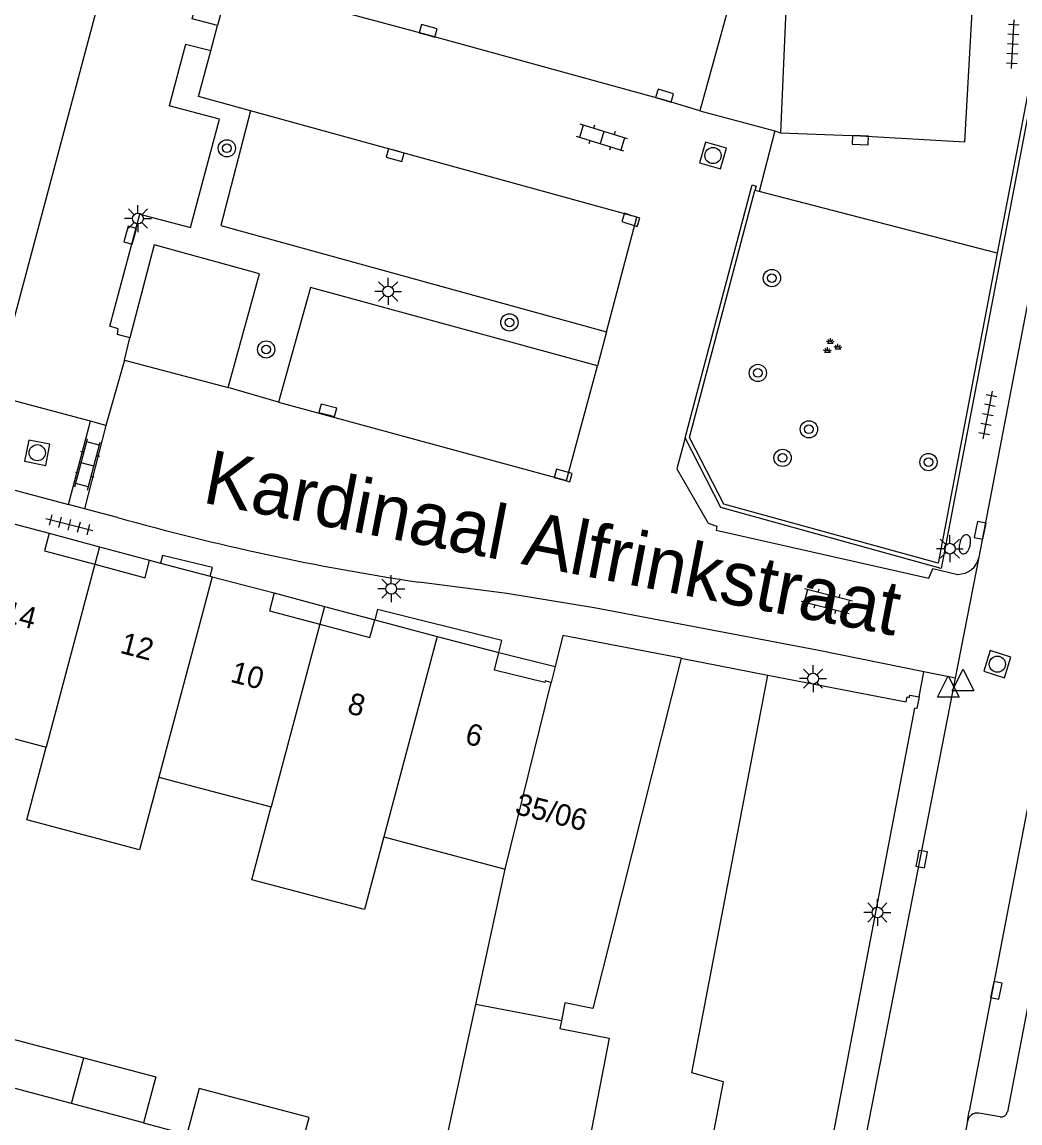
# Model space of a CAD drawing. Extents: x 132998 to 136004, y 396998 to 398512.
# Drawn here: x 133628.5 to 133674.7, y 397657 to 397708.1 of the extents above; entities that cross this region are included whole.
import ezdxf

# ---------------------------------------------------------------- set-up
doc = ezdxf.new("R2010")
doc.units = 0
for name, color, linetype in [('gg-afsc-erfafscheiding', 7, 'Continuous'), ('gg-afsc-hekwerk', 7, 'Continuous'), ('gg-afsc-muur', 7, 'Continuous'), ('gg-anno-huisnummerreeks BGT', 7, 'Continuous'), ('gg-anno-openbare ruimte label', 7, 'Continuous'), ('gg-bbg-gedigitaliseerde bebouwing', 7, 'Continuous'), ('gg-bbg-gedigitaliseerde bijgebouw', 7, 'Continuous'), ('gg-bbg-hoofdgebouw', 7, 'Continuous'), ('gg-bbg-luifel en loopbrug', 7, 'Continuous'), ('gg-bbg-onder overbouw', 7, 'Continuous'), ('gg-bbg-pand overbouw', 7, 'Continuous'), ('gg-bbg-pandafbakening', 7, 'Continuous'), ('gg-bbg-tussenscheiding', 7, 'Continuous'), ('gg-bbg-tussenscheiding niveau 01', 7, 'Continuous'), ('gg-knt-verharding', 7, 'Continuous'), ('gg-knt-verharding nz', 7, 'Continuous'), ('gt-grn-weggrens', 7, 'Continuous'), ('gt-symb-boom', 7, 'Continuous'), ('gt-symb-brandkraan', 7, 'Continuous'), ('gt-symb-groenvak', 7, 'Continuous'), ('gt-symb-klinker verharding', 7, 'Continuous'), ('gt-symb-kolk', 7, 'Continuous'), ('gt-symb-lichtmast', 7, 'Continuous'), ('gt-symb-rioolschacht', 7, 'Continuous'), ('gt-symb-tegel verharding', 7, 'Continuous'), ('gt-symb-waterafsluiter', 7, 'Continuous')]:
    doc.layers.add(name, color=color, linetype=linetype)

# ---------------------------------------------------------------- blocks, each defined once
blk = doc.blocks.new('gt0-TEG1')
at = {"layer": 'gt-symb-tegel verharding'}
for p, q in [((-1.125, 0), (1.125, 0)), ((-0.9, -0.25), (-0.9, 0.25)), ((-0.45, -0.25), (-0.45, 0.25)), ((0, -0.25), (0, 0.25)), ((0.45, -0.25), (0.45, 0.25)), ((0.9, -0.25), (0.9, 0.25))]:
    blk.add_line(p, q, dxfattribs=at)
blk = doc.blocks.new('gt0-KL1')
at = {"layer": 'gt-symb-klinker verharding'}
for p, q in [((-1.15, 0.3), (1.15, 0.3)), ((-1, -0.3), (-1, 0.3)), ((-0.5, 0.3), (-0.5, 0.45)), ((0, -0.3), (0, 0.3)), ((0.5, 0.3), (0.5, 0.45)), ((1, -0.3), (1, 0.3)), ((-1.15, -0.3), (1.15, -0.3)), ((-0.5, -0.45), (-0.5, -0.3)), ((0.5, -0.45), (0.5, -0.3))]:
    blk.add_line(p, q, dxfattribs=at)
blk = doc.blocks.new('gt0-RS')
at = {"layer": 'gt-symb-rioolschacht'}
blk.add_lwpolyline([(-0.5, -0.5), (0.5, -0.5), (0.5, 0.5), (-0.5, 0.5)], close=True, dxfattribs=at)
blk.add_circle((0, 0), 0.375, dxfattribs=at)
blk = doc.blocks.new('gt0-KOLK')
at = {"layer": 'gt-symb-kolk'}
blk.add_lwpolyline([(0, 0), (0.375, 0), (0.375, 0.4), (-0.375, 0.4), (-0.375, 0), (0, 0)], dxfattribs=at)
blk = doc.blocks.new('gt0-BOOM')
at = {"layer": 'gt-symb-boom'}
for radius in [0.4, 0.2]:
    blk.add_circle((0, 0), radius, dxfattribs=at)
blk = doc.blocks.new('gt0-GRVAK')
at = {"layer": 'gt-symb-groenvak'}
for p, q in [((-0.11, 0.189), (-0.228, 0.24)), ((-0.182, 0.153), (0.088, 0.153)), ((-0.091, 0.211), (-0.156, 0.322)), ((-0.047, 0.214), (-0.047, 0.393)), ((-0.004, 0.211), (0.061, 0.322)), ((0.015, 0.189), (0.133, 0.24)), ((0.262, -0.052), (0.197, 0.059)), ((0.305, -0.049), (0.305, 0.13)), ((0.349, -0.052), (0.414, 0.059)), ((-0.245, -0.228), (-0.363, -0.177)), ((-0.318, -0.264), (-0.047, -0.264)), ((-0.226, -0.206), (-0.291, -0.095)), ((-0.183, -0.203), (-0.183, -0.024)), ((-0.139, -0.206), (-0.074, -0.095)), ((-0.12, -0.228), (-0.002, -0.177)), ((0.243, -0.074), (0.125, -0.023)), ((0.17, -0.11), (0.441, -0.11)), ((0.368, -0.074), (0.486, -0.023))]:
    blk.add_line(p, q, dxfattribs=at)
blk = doc.blocks.new('gt0-LMAST')
at = {"layer": 'gt-symb-lichtmast'}
for p, q in [((-0.005, 0.246), (-0.005, 0.621)), ((-0.182, 0.173), (-0.447, 0.438)), ((0.172, 0.173), (0.437, 0.438)), ((-0.255, -0.004), (-0.63, -0.004)), ((-0.182, -0.181), (-0.447, -0.446)), ((-0.005, -0.254), (-0.005, -0.629)), ((0.437, -0.446), (0.172, -0.181)), ((0.245, -0.004), (0.62, -0.004))]:
    blk.add_line(p, q, dxfattribs=at)
blk.add_circle((-0.005, -0.004), 0.25, dxfattribs=at)
blk = doc.blocks.new('gt0-BR')
at = {"layer": 'gt-symb-brandkraan'}
for centre, radius, start, end in [((-0.244, 0), 0.206, 107.5669, 252.4331), ((0.599, -2.664), 3, 106.892, 107.5669), ((0, -0.691), 0.938, 73.108, 106.892), ((-0.599, -2.664), 3, 72.4331, 73.108), ((0.244, 0), 0.206, 287.567, 72.4331), ((0.599, 2.664), 3, 252.4331, 253.108), ((0, 0.691), 0.938, 253.108, 286.8921), ((-0.599, 2.664), 3, 286.8921, 287.567)]:
    blk.add_arc(centre, radius, start, end, dxfattribs=at)
blk = doc.blocks.new('gt0-WAFSL')
at = {"layer": 'gt-symb-waterafsluiter'}
for p, q in [((-0.5, -0.333), (0, 0.667)), ((0, 0.667), (0.5, -0.333)), ((0.5, -0.333), (-0.5, -0.333))]:
    blk.add_line(p, q, dxfattribs=at)

msp = doc.modelspace()

# ---------------------------------------------------------------- linework, layer by layer
at = {"layer": 'gg-afsc-erfafscheiding'}
msp.add_line((133634.128, 397657.05), (133636.141, 397656.512), dxfattribs=at)
at = {"layer": 'gg-afsc-hekwerk'}
for p, q in [((133662.654, 397700.205), (133662.457, 397700.256)), ((133673.683, 397697.355), (133662.654, 397700.205))]:
    msp.add_line(p, q, dxfattribs=at)
at = {"layer": 'gg-afsc-muur'}
for p, q in [((133679.404, 397727.312), (133673.683, 397697.355)), ((133676.965, 397713.527), (133671.086, 397682.743)), ((133673.683, 397697.355), (133670.938, 397682.981)), ((133659.037, 397678.583), (133660.057, 397678.39))]:
    msp.add_line(p, q, dxfattribs=at)
for points in [[(133659.219, 397688.791), (133662.326, 397700.513), (133662.512, 397700.463), (133662.457, 397700.256)], [(133670.938, 397682.981), (133661.009, 397685.72), (133659.423, 397688.81), (133662.457, 397700.256)], [(133671.086, 397682.743), (133660.878, 397685.559), (133659.219, 397688.791)]]:
    msp.add_lwpolyline(points, dxfattribs=at)
at = {"layer": 'gg-bbg-gedigitaliseerde bebouwing'}
for p, q in [((133624.407, 397675.848), (133629.617, 397674.462)), ((133634.845, 397673.073), (133640.045, 397671.69)), ((133645.263, 397670.304), (133650.88, 397668.811)), ((133649.52, 397662.541), (133650.88, 397668.811))]:
    msp.add_line(p, q, dxfattribs=at)
for points in [[(133659.037, 397678.583), (133654.946, 397662.357), (133653.65, 397662.606), (133653.491, 397661.781)], [(133655.15, 397628.455), (133660.998, 397658.956), (133659.526, 397659.368), (133663.055, 397677.79)], [(133634.845, 397673.073), (133633.949, 397669.702), (133628.721, 397671.092), (133629.617, 397674.462)], [(133645.263, 397670.304), (133644.366, 397666.933), (133639.149, 397668.32), (133640.045, 397671.69)], [(133642.472, 397631.33), (133646.222, 397647.335), (133649.52, 397662.541)], [(133653.491, 397661.781), (133653.421, 397661.418), (133655.7, 397660.98), (133654.378, 397654.106)]]:
    msp.add_lwpolyline(points, dxfattribs=at)
at = {"layer": 'gg-bbg-gedigitaliseerde bijgebouw'}
for p, q in [((133628.036, 397660.944), (133631.361, 397660.063)), ((133630.793, 397657.941), (133627.475, 397658.827)), ((133634.128, 397657.05), (133630.793, 397657.941))]:
    msp.add_line(p, q, dxfattribs=at)
msp.add_lwpolyline([(133631.361, 397660.063), (133634.7, 397659.178), (133634.128, 397657.05)], dxfattribs=at)
at = {"layer": 'gg-bbg-hoofdgebouw'}
for p, q in [((133626.878, 397685.133), (133629.757, 397684.374)), ((133634.412, 397683.12), (133634.921, 397682.987)), ((133634.921, 397682.987), (133637.214, 397682.385)), ((133637.214, 397682.385), (133637.315, 397682.359)), ((133637.315, 397682.359), (133640.181, 397681.608)), ((133644.839, 397680.355), (133644.844, 397680.354)), ((133644.844, 397680.354), (133647.734, 397679.596)), ((133647.734, 397679.596), (133650.594, 397678.846))]:
    msp.add_line(p, q, dxfattribs=at)
for points in [[(133627.399, 397692.591), (133627.663, 397692.521), (133635.288, 397721.118)], [(133659.037, 397678.583), (133653.55, 397679.638), (133653.195, 397678.201)], [(133663.055, 397677.79), (133669.459, 397676.564), (133669.503, 397676.79), (133669.611, 397676.769), (133669.632, 397676.877), (133670.064, 397676.793)], [(133670.064, 397676.793), (133669.959, 397676.253), (133669.851, 397676.274), (133660.537, 397627.523)]]:
    msp.add_lwpolyline(points, dxfattribs=at)
at = {"layer": 'gg-bbg-luifel en loopbrug'}
msp.add_lwpolyline([(133641.405, 397655.8), (133641.8, 397657.296), (133636.704, 397658.647), (133636.141, 397656.512)], dxfattribs=at)
at = {"layer": 'gg-bbg-onder overbouw'}
for points in [[(133629.757, 397684.374), (133629.538, 397683.56), (133631.87, 397682.933)], [(133631.87, 397682.933), (133634.199, 397682.307), (133634.412, 397683.12)], [(133640.181, 397681.608), (133639.963, 397680.779), (133642.298, 397680.161)], [(133642.298, 397680.161), (133644.614, 397679.547), (133644.839, 397680.355)], [(133653.013, 397677.464), (133652.741, 397677.531), (133652.722, 397677.453), (133650.392, 397678.031), (133650.594, 397678.846)]]:
    msp.add_lwpolyline(points, dxfattribs=at)
at = {"layer": 'gg-bbg-pand overbouw'}
for p, q in [((133629.757, 397684.374), (133632.086, 397683.746)), ((133632.086, 397683.746), (133634.412, 397683.12)), ((133640.181, 397681.608), (133642.516, 397680.98)), ((133642.516, 397680.98), (133644.839, 397680.355)), ((133650.594, 397678.846), (133653.195, 397678.201))]:
    msp.add_line(p, q, dxfattribs=at)
at = {"layer": 'gg-bbg-pandafbakening'}
msp.add_line((133653.195, 397678.201), (133653.013, 397677.464), dxfattribs=at)
at = {"layer": 'gg-bbg-tussenscheiding'}
for p, q in [((133631.87, 397682.933), (133629.617, 397674.462)), ((133637.315, 397682.359), (133634.845, 397673.073)), ((133642.298, 397680.161), (133640.045, 397671.69)), ((133647.734, 397679.596), (133645.263, 397670.304)), ((133650.88, 397668.811), (133653.013, 397677.464)), ((133653.491, 397661.781), (133649.52, 397662.541)), ((133630.793, 397657.941), (133631.361, 397660.063))]:
    msp.add_line(p, q, dxfattribs=at)
at = {"layer": 'gg-bbg-tussenscheiding niveau 01'}
for p, q in [((133632.086, 397683.746), (133631.87, 397682.933)), ((133642.516, 397680.98), (133642.298, 397680.161))]:
    msp.add_line(p, q, dxfattribs=at)
at = {"layer": 'gg-knt-verharding'}
for p, q in [((133638.105, 397709.933), (133637.553, 397707.902)), ((133659.907, 397703.94), (133663.386, 397703.015)), ((133663.386, 397703.015), (133662.654, 397700.205)), ((133663.386, 397703.015), (133663.645, 397702.933)), ((133573.036, 397701.017), (133630.659, 397685.707)), ((133672.84, 397683.259), (133675.574, 397697.514)), ((133655.572, 397693.705), (133655.168, 397692.133)), ((133633.251, 397692.388), (133633.496, 397693.43)), ((133633.251, 397692.388), (133632.391, 397689.373)), ((133640.391, 397690.454), (133638.053, 397691.121)), ((133630.659, 397685.707), (133631.681, 397689.561)), ((133632.391, 397689.373), (133631.396, 397685.511)), ((133632.391, 397689.373), (133631.681, 397689.561)), ((133631.396, 397685.511), (133630.659, 397685.707)), ((133632.926, 397685.104), (133631.396, 397685.511)), ((133671.745, 397677.651), (133672.84, 397683.259)), ((133660.057, 397678.39), (133663.055, 397677.79)), ((133671.745, 397677.651), (133670.283, 397677.948)), ((133659.984, 397617.411), (133671.745, 397677.651)), ((133673.816, 397657.33), (133672.837, 397657.504))]:
    msp.add_line(p, q, dxfattribs=at)
for points in [[(133663.645, 397702.933), (133667.346, 397702.783), (133672.175, 397702.508), (133672.739, 397712.397), (133673.996, 397741.005), (133668.64, 397741.252)], [(133637.553, 397707.902), (133636.383, 397708.208), (133638.873, 397717.528)], [(133640.141, 397717.22), (133664.104, 397713.628), (133663.645, 397702.933)], [(133638.105, 397709.933), (133639.529, 397715.258), (133661.376, 397709.284), (133659.907, 397703.94)], [(133637.252, 397706.727), (133636.077, 397707.027), (133635.314, 397704.176)], [(133639.09, 397703.951), (133636.683, 397704.61), (133637.252, 397706.727)], [(133631.681, 397689.561), (133579.126, 397703.561), (133579.475, 397705.003)], [(133633.966, 397699.155), (133636.312, 397698.54), (133637.644, 397703.561), (133635.314, 397704.176)], [(133639.09, 397703.951), (133637.717, 397698.635), (133655.572, 397693.705)], [(133633.496, 397693.43), (133632.926, 397693.581), (133632.962, 397693.849), (133632.577, 397693.974), (133633.966, 397699.155)], [(133638.053, 397691.121), (133639.498, 397696.393), (133634.627, 397697.736), (133633.496, 397693.43)], [(133655.168, 397692.133), (133641.87, 397695.762), (133640.391, 397690.454)], [(133659.219, 397688.791), (133658.844, 397687.359), (133660.288, 397684.838), (133660.695, 397684.702), (133660.662, 397684.521), (133670.51, 397682.294), (133670.703, 397682.737), (133671.858, 397682.469)], [(133637.214, 397682.385), (133637.319, 397682.786), (133635.016, 397683.348), (133634.921, 397682.987)], [(133670.283, 397677.948), (133665.347, 397678.95), (133655.009, 397680.91), (133650.961, 397681.581), (133646.891, 397682.103)], [(133650.594, 397678.846), (133650.732, 397679.404), (133644.969, 397680.832), (133644.844, 397680.354)], [(133677.444, 397674.746), (133677.386, 397674.398), (133674.15, 397657.563)], [(133672.299, 397657.13), (133667.463, 397631.605), (133667.911, 397629.653), (133668.085, 397629.597)]]:
    msp.add_lwpolyline(points, dxfattribs=at)
for centre, radius, start, end in [((133663.976, 397795.601), 114.777, 254.30442, 261.43939), ((133671.847, 397683.488), 1.019, 270.5968, 347.0353), ((133672.776, 397657.018), 0.49, 82.8328, 166.7787), ((133673.859, 397657.624), 0.297, 261.5831, 348.2165)]:
    msp.add_arc(centre, radius, start, end, dxfattribs=at)
at = {"layer": 'gg-knt-verharding nz'}
for p, q in [((133633.251, 397692.388), (133638.053, 397691.121)), ((133675.73, 397675.034), (133672.389, 397657.587)), ((133672.299, 397657.13), (133672.389, 397657.587))]:
    msp.add_line(p, q, dxfattribs=at)
for points in [[(133659.907, 397703.94), (133658.214, 397704.454), (133647.265, 397707.465), (133638.105, 397709.933)], [(133655.572, 397693.705), (133656.978, 397699.022), (133639.09, 397703.951)], [(133640.391, 397690.454), (133653.731, 397686.822), (133655.168, 397692.133)]]:
    msp.add_lwpolyline(points, dxfattribs=at)
at = {"layer": 'gt-grn-weggrens'}
for p, q in [((133637.252, 397706.727), (133637.553, 397707.902)), ((133670.064, 397676.793), (133670.283, 397677.948))]:
    msp.add_line(p, q, dxfattribs=at)

# ---------------------------------------------------------------- block references
at = {"layer": 'gt-symb-boom'}
for p in [(133637.991, 397702.211), (133663.242, 397696.197), (133651.082, 397694.143), (133639.812, 397692.889), (133662.592, 397691.801), (133664.958, 397689.19), (133663.739, 397687.867), (133670.497, 397687.672)]:
    msp.add_blockref('gt0-BOOM', p, dxfattribs=at)
at = {"layer": 'gt-symb-brandkraan', "rotation": 75.69972255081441}
msp.add_blockref('gt0-BR', (133672.181, 397683.857), dxfattribs=at)
at = {"layer": 'gt-symb-groenvak'}
msp.add_blockref('gt0-GRVAK', (133665.999, 397693.027), dxfattribs=at)
at = {"layer": 'gt-symb-klinker verharding'}
for p, rotation in [((133655.372, 397702.701), 162.7793006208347), ((133631.536, 397687.562), 75.1718914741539), ((133665.786, 397681.218), 165.40804379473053)]:
    msp.add_blockref('gt0-KL1', p, dxfattribs=dict(at, rotation=rotation))
at = {"layer": 'gt-symb-kolk'}
for p, rotation in [((133647.265, 397707.465), -15.370725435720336), ((133658.214, 397704.454), -16.913217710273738), ((133667.345, 397702.783), 177.64984047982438), ((133645.845, 397702.092), 164.6292745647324), ((133656.771, 397699.089), 162.05443695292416), ((133633.709, 397698.135), 74.75492966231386), ((133642.62, 397689.872), -14.647375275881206), ((133653.516, 397686.861), -15.425970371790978), ((133673.087, 397684.467), 78.4092631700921), ((133669.987, 397669.311), -100.71464389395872), ((133673.445, 397663.229), -101.47848203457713)]:
    msp.add_blockref('gt0-KOLK', p, dxfattribs=dict(at, rotation=rotation))
at = {"layer": 'gt-symb-lichtmast'}
for p in [(133633.878, 397698.961), (133645.469, 397695.581), (133671.491, 397683.662), (133645.612, 397681.804), (133665.154, 397677.64), (133668.135, 397666.803)]:
    msp.add_blockref('gt0-LMAST', p, dxfattribs=at)
at = {"layer": 'gt-symb-rioolschacht'}
for p, rotation in [((133660.513, 397701.875), 163.92082762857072), ((133629.207, 397688.104), 168.70129979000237), ((133673.689, 397678.307), 72.54344186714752)]:
    msp.add_blockref('gt0-RS', p, dxfattribs=dict(at, rotation=rotation))
at = {"layer": 'gt-symb-tegel verharding'}
for p, rotation in [((133674.405, 397707.037), 87.13473427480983), ((133673.247, 397689.86), 78.92612884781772), ((133630.69, 397684.764), 165.40804379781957)]:
    msp.add_blockref('gt0-TEG1', p, dxfattribs=dict(at, rotation=rotation))
at = {"layer": 'gt-symb-waterafsluiter'}
for p in [(133672.098, 397677.41), (133671.413, 397677.106)]:
    msp.add_blockref('gt0-WAFSL', p, dxfattribs=at)

# ---------------------------------------------------------------- texts
at = {"layer": 'gg-anno-huisnummerreeks BGT'}
for s, rotation, p in [('14', 345.2, (133627.57, 397680.297)), ('12', 345.3, (133632.997, 397678.838)), ('10', 345.3, (133638.107, 397677.499)), ('8', 345.3, (133643.521, 397676.049)), ('6', 345.7, (133648.974, 397674.635)), ('35/06', 345.9, (133651.293, 397671.376))]:
    msp.add_text(s, height=1, rotation=rotation, dxfattribs=at).set_placement(p)
at = {"layer": 'gg-anno-openbare ruimte label'}
msp.add_text('Kardinaal Alfrinkstraat', height=2.5, rotation=349.1, dxfattribs=at).set_placement((133636.803, 397685.805))

doc.saveas('drawing.dxf')
